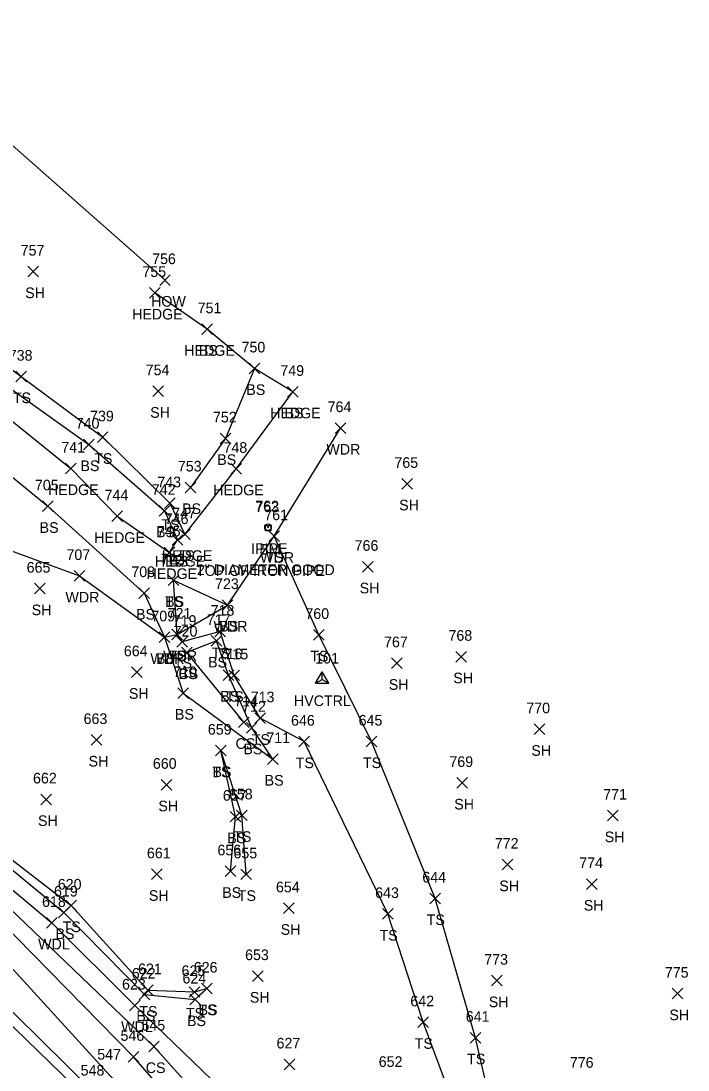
# Model space of a CAD drawing. Extents: x 1611034 to 1613847, y 761049 to 763902.
# Drawn here: x 1611914.9 to 1612040.4, y 763048.6 to 763246 of the extents above; entities that cross this region are included whole.
import ezdxf

# ---------------------------------------------------------------- set-up
doc = ezdxf.new("R2010")
doc.units = 0
for name, color, linetype in [('C_A', 7, 'Continuous'), ('C_C', 7, 'Continuous'), ('C_I', 7, 'Continuous'), ('CPBM', 7, 'Continuous'), ('CPSM', 7, 'Continuous'), ('L_A', 7, 'Continuous'), ('L_I', 7, 'Continuous'), ('L_TIC', 7, 'Continuous'), ('LAHR', 7, 'Continuous'), ('LAWA', 7, 'Continuous'), ('LBC', 7, 'Continuous'), ('LELB', 7, 'Continuous'), ('M_A', 7, 'Continuous'), ('M_C', 7, 'Continuous'), ('M_I', 7, 'Continuous'), ('MPIP', 7, 'Continuous'), ('PSP', 7, 'Continuous')]:
    doc.layers.add(name, color=color, linetype=linetype)

msp = doc.modelspace()

# ---------------------------------------------------------------- linework, layer by layer
at = {"layer": 'CPBM'}
for p, q in [((1611960.93, 763150.08), (1611960.93, 763151.08)), ((1611960.93, 763151.08), (1611961.93, 763151.08)), ((1611961.43, 763150.58), (1611961.43, 763150.58)), ((1611961.43, 763150.58), (1611961.43, 763150.58)), ((1611961.93, 763151.08), (1611961.93, 763150.08)), ((1611961.93, 763150.08), (1611960.93, 763150.08))]:
    msp.add_line(p, q, dxfattribs=at)
at = {"layer": 'CPSM'}
for p, q in [((1611970.32, 763121.37), (1611971.57, 763123.54)), ((1611972.82, 763121.37), (1611971.57, 763123.54)), ((1611971.57, 763122.09), (1611971.57, 763123.54)), ((1611970.32, 763121.37), (1611971.57, 763122.09)), ((1611970.32, 763121.37), (1611972.82, 763121.37)), ((1611971.57, 763122.09), (1611971.57, 763122.09)), ((1611971.57, 763122.09), (1611972.82, 763121.37))]:
    msp.add_line(p, q, dxfattribs=at)
at = {"layer": 'L_TIC'}
for points in [[(1611916.23, 763197.85), (1611918.23, 763199.85)], [(1611918.23, 763197.85), (1611916.23, 763199.85)], [(1611941.01, 763196.25), (1611943.01, 763198.25)], [(1611943.01, 763196.25), (1611941.01, 763198.25)], [(1611939.12, 763193.83), (1611941.12, 763195.83)], [(1611941.12, 763193.83), (1611939.12, 763195.83)], [(1611948.94, 763187), (1611950.94, 763189)], [(1611950.94, 763187), (1611948.94, 763189)], [(1611948.94, 763187), (1611950.94, 763189)], [(1611950.94, 763187), (1611948.94, 763189)], [(1611957.86, 763179.63), (1611959.86, 763181.63)], [(1611959.86, 763179.63), (1611957.86, 763181.63)], [(1611957.86, 763179.63), (1611959.86, 763181.63)], [(1611959.86, 763179.63), (1611957.86, 763181.63)], [(1611913.99, 763178.09), (1611915.99, 763180.09)], [(1611915.99, 763178.09), (1611913.99, 763180.09)], [(1611939.74, 763175.34), (1611941.74, 763177.34)], [(1611941.74, 763175.34), (1611939.74, 763177.34)], [(1611965.07, 763175.23), (1611967.07, 763177.23)], [(1611967.07, 763175.23), (1611965.07, 763177.23)], [(1611965.07, 763175.23), (1611967.07, 763177.23)], [(1611967.07, 763175.23), (1611965.07, 763177.23)], [(1611974, 763168.4), (1611976, 763170.4)], [(1611976, 763168.4), (1611974, 763170.4)], [(1611929.29, 763166.67), (1611931.29, 763168.67)], [(1611931.29, 763166.67), (1611929.29, 763168.67)], [(1611952.39, 763166.46), (1611954.39, 763168.46)], [(1611954.39, 763166.46), (1611952.39, 763168.46)], [(1611926.67, 763165.3), (1611928.67, 763167.3)], [(1611928.67, 763165.3), (1611926.67, 763167.3)], [(1611923.3, 763160.79), (1611925.3, 763162.79)], [(1611925.3, 763160.79), (1611923.3, 763162.79)], [(1611954.37, 763160.74), (1611956.37, 763162.74)], [(1611956.37, 763160.74), (1611954.37, 763162.74)], [(1611945.79, 763157.23), (1611947.79, 763159.23)], [(1611947.79, 763157.23), (1611945.79, 763159.23)], [(1611986.56, 763157.91), (1611988.56, 763159.91)], [(1611988.56, 763157.91), (1611986.56, 763159.91)], [(1611918.99, 763153.68), (1611920.99, 763155.68)], [(1611920.99, 763153.68), (1611918.99, 763155.68)], [(1611940.9, 763152.84), (1611942.9, 763154.84)], [(1611942.9, 763152.84), (1611940.9, 763154.84)], [(1611941.93, 763154.25), (1611943.93, 763156.25)], [(1611943.93, 763154.25), (1611941.93, 763156.25)], [(1611932.01, 763151.8), (1611934.01, 763153.8)], [(1611934.01, 763151.8), (1611932.01, 763153.8)], [(1611943.38, 763147.34), (1611945.38, 763149.34)], [(1611945.38, 763147.34), (1611943.38, 763149.34)], [(1611943.38, 763147.34), (1611945.38, 763149.34)], [(1611945.38, 763147.34), (1611943.38, 763149.34)], [(1611944.72, 763148.4), (1611946.72, 763150.4)], [(1611946.72, 763148.4), (1611944.72, 763150.4)], [(1611944.72, 763148.4), (1611946.72, 763150.4)], [(1611946.72, 763148.4), (1611944.72, 763150.4)], [(1611961.53, 763148.06), (1611963.53, 763150.06)], [(1611963.53, 763148.06), (1611961.53, 763150.06)], [(1611961.53, 763148.06), (1611963.53, 763150.06)], [(1611963.53, 763148.06), (1611961.53, 763150.06)], [(1611941.84, 763145), (1611943.84, 763147)], [(1611943.84, 763145), (1611941.84, 763147)], [(1611979.13, 763142.3), (1611981.13, 763144.3)], [(1611981.13, 763142.3), (1611979.13, 763144.3)], [(1611924.92, 763140.58), (1611926.92, 763142.58)], [(1611926.92, 763140.58), (1611924.92, 763142.58)], [(1611942.6, 763139.75), (1611944.6, 763141.75)], [(1611944.6, 763139.75), (1611942.6, 763141.75)], [(1611942.6, 763139.75), (1611944.6, 763141.75)], [(1611944.6, 763139.75), (1611942.6, 763141.75)], [(1611917.46, 763138.19), (1611919.46, 763140.19)], [(1611919.46, 763138.19), (1611917.46, 763140.19)], [(1611937.12, 763137.36), (1611939.12, 763139.36)], [(1611939.12, 763137.36), (1611937.12, 763139.36)], [(1611952.78, 763135.1), (1611954.78, 763137.1)], [(1611954.78, 763135.1), (1611952.78, 763137.1)], [(1611952.78, 763135.1), (1611954.78, 763137.1)], [(1611954.78, 763135.1), (1611952.78, 763137.1)], [(1611940.9, 763129.03), (1611942.9, 763131.03)], [(1611942.9, 763129.03), (1611940.9, 763131.03)], [(1611940.9, 763129.03), (1611942.9, 763131.03)], [(1611942.9, 763129.03), (1611940.9, 763131.03)], [(1611943.3, 763129.53), (1611945.3, 763131.53)], [(1611945.3, 763129.53), (1611943.3, 763131.53)], [(1611943.3, 763129.53), (1611945.3, 763131.53)], [(1611945.3, 763129.53), (1611943.3, 763131.53)], [(1611951.39, 763130.09), (1611953.39, 763132.09)], [(1611953.39, 763130.09), (1611951.39, 763132.09)], [(1611969.91, 763129.49), (1611971.91, 763131.49)], [(1611971.91, 763129.49), (1611969.91, 763131.49)], [(1611944.26, 763128.19), (1611946.26, 763130.19)], [(1611946.26, 763128.19), (1611944.26, 763130.19)], [(1611950.67, 763128.35), (1611952.67, 763130.35)], [(1611952.67, 763128.35), (1611950.67, 763130.35)], [(1611945.1, 763126.17), (1611947.1, 763128.17)], [(1611947.1, 763126.17), (1611945.1, 763128.17)], [(1611945.1, 763126.17), (1611947.1, 763128.17)], [(1611947.1, 763126.17), (1611945.1, 763128.17)], [(1611996.73, 763125.38), (1611998.73, 763127.38)], [(1611998.73, 763125.38), (1611996.73, 763127.38)], [(1611984.61, 763124.15), (1611986.61, 763126.15)], [(1611986.61, 763124.15), (1611984.61, 763126.15)], [(1611935.73, 763122.46), (1611937.73, 763124.46)], [(1611937.73, 763122.46), (1611935.73, 763124.46)], [(1611952.96, 763121.93), (1611954.96, 763123.93)], [(1611954.96, 763121.93), (1611952.96, 763123.93)], [(1611954, 763121.87), (1611956, 763123.87)], [(1611956, 763121.87), (1611954, 763123.87)], [(1611944.43, 763118.54), (1611946.43, 763120.54)], [(1611946.43, 763118.54), (1611944.43, 763120.54)], [(1611955.84, 763113.03), (1611957.84, 763115.03)], [(1611957.84, 763113.03), (1611955.84, 763115.03)], [(1611958.93, 763113.8), (1611960.93, 763115.8)], [(1611960.93, 763113.8), (1611958.93, 763115.8)], [(1611957.31, 763112.02), (1611959.31, 763114.02)], [(1611959.31, 763112.02), (1611957.31, 763114.02)], [(1612011.41, 763111.73), (1612013.41, 763113.73)], [(1612013.41, 763111.73), (1612011.41, 763113.73)], [(1611928.15, 763109.71), (1611930.15, 763111.71)], [(1611930.15, 763109.71), (1611928.15, 763111.71)], [(1611967.18, 763109.4), (1611969.18, 763111.4)], [(1611969.18, 763109.4), (1611967.18, 763111.4)], [(1611979.83, 763109.42), (1611981.83, 763111.42)], [(1611981.83, 763109.42), (1611979.83, 763111.42)], [(1611951.49, 763107.71), (1611953.49, 763109.71)], [(1611953.49, 763107.71), (1611951.49, 763109.71)], [(1611951.49, 763107.71), (1611953.49, 763109.71)], [(1611953.49, 763107.71), (1611951.49, 763109.71)], [(1611961.31, 763106.12), (1611963.31, 763108.12)], [(1611963.31, 763106.12), (1611961.31, 763108.12)], [(1611941.27, 763101.29), (1611943.27, 763103.29)], [(1611943.27, 763101.29), (1611941.27, 763103.29)], [(1611996.91, 763101.63), (1611998.91, 763103.63)], [(1611998.91, 763101.63), (1611996.91, 763103.63)], [(1611918.64, 763098.53), (1611920.64, 763100.53)], [(1611920.64, 763098.53), (1611918.64, 763100.53)], [(1611954.29, 763095.28), (1611956.29, 763097.28)], [(1611956.29, 763095.28), (1611954.29, 763097.28)], [(1611955.44, 763095.53), (1611957.44, 763097.53)], [(1611957.44, 763095.53), (1611955.44, 763097.53)], [(1612025.21, 763095.48), (1612027.21, 763097.48)], [(1612027.21, 763095.48), (1612025.21, 763097.48)], [(1612005.39, 763086.26), (1612007.39, 763088.26)], [(1612007.39, 763086.26), (1612005.39, 763088.26)], [(1611939.5, 763084.44), (1611941.5, 763086.44)], [(1611941.5, 763084.44), (1611939.5, 763086.44)], [(1611953.33, 763085), (1611955.33, 763087)], [(1611955.33, 763085), (1611953.33, 763087)], [(1611956.29, 763084.43), (1611958.29, 763086.43)], [(1611958.29, 763084.43), (1611956.29, 763086.43)], [(1612021.28, 763082.6), (1612023.28, 763084.6)], [(1612023.28, 763082.6), (1612021.28, 763084.6)], [(1611991.81, 763079.89), (1611993.81, 763081.89)], [(1611993.81, 763079.89), (1611991.81, 763081.89)], [(1611923.35, 763078.56), (1611925.35, 763080.56)], [(1611925.35, 763078.56), (1611923.35, 763080.56)], [(1611964.28, 763078.05), (1611966.28, 763080.05)], [(1611966.28, 763078.05), (1611964.28, 763080.05)], [(1611921.98, 763077.25), (1611923.98, 763079.25)], [(1611923.98, 763077.25), (1611921.98, 763079.25)], [(1611982.94, 763076.97), (1611984.94, 763078.97)], [(1611984.94, 763076.97), (1611982.94, 763078.97)], [(1611919.73, 763075.3), (1611921.73, 763077.3)], [(1611921.73, 763075.3), (1611919.73, 763077.3)], [(1611958.48, 763065.29), (1611960.48, 763067.29)], [(1611960.48, 763065.29), (1611958.48, 763067.29)], [(1612003.41, 763064.43), (1612005.41, 763066.43)], [(1612005.41, 763064.43), (1612003.41, 763066.43)], [(1611937.18, 763061.8), (1611939.18, 763063.8)], [(1611939.18, 763061.8), (1611937.18, 763063.8)], [(1611937.78, 763062.64), (1611939.78, 763064.64)], [(1611939.78, 763062.64), (1611937.78, 763064.64)], [(1611946.53, 763062.29), (1611948.53, 763064.29)], [(1611948.53, 763062.29), (1611946.53, 763064.29)], [(1611948.88, 763062.93), (1611950.88, 763064.93)], [(1611950.88, 763062.93), (1611948.88, 763064.93)], [(1611948.88, 763062.93), (1611950.88, 763064.93)], [(1611950.88, 763062.93), (1611948.88, 763064.93)], [(1612037.37, 763061.98), (1612039.37, 763063.98)], [(1612039.37, 763061.98), (1612037.37, 763063.98)], [(1611935.34, 763059.75), (1611937.34, 763061.75)], [(1611937.34, 763059.75), (1611935.34, 763061.75)], [(1611946.71, 763060.88), (1611948.71, 763062.88)], [(1611948.71, 763060.88), (1611946.71, 763062.88)], [(1611989.56, 763056.6), (1611991.56, 763058.6)], [(1611991.56, 763056.6), (1611989.56, 763058.6)], [(1611938.94, 763052.04), (1611940.94, 763054.04)], [(1611940.94, 763052.04), (1611938.94, 763054.04)], [(1611999.41, 763053.68), (1612001.41, 763055.68)], [(1612001.41, 763053.68), (1611999.41, 763055.68)], [(1611935.07, 763050.1), (1611937.07, 763052.1)], [(1611937.07, 763050.1), (1611935.07, 763052.1)], [(1611964.4, 763048.66), (1611966.4, 763050.66)], [(1611966.4, 763048.66), (1611964.4, 763050.66)]]:
    msp.add_lwpolyline(points, dxfattribs=at)
at = {"layer": 'LAHR'}
for points in [[(1611870.5, 763246), (1611861.19, 763216.3), (1611876.92, 763202.2), (1611887.58, 763190.23), (1611909.6, 763173.67), (1611924.3, 763161.79), (1611933.01, 763152.8), (1611942.84, 763146), (1611944.38, 763148.34), (1611945.72, 763149.4), (1611955.37, 763161.74), (1611966.07, 763176.23)], [(1611949.94, 763188), (1611940.12, 763194.83)]]:
    msp.add_lwpolyline(points, dxfattribs=at)
at = {"layer": 'LAWA'}
for points in [[(1611802.19, 763242.63), (1611826.4, 763223.06), (1611842.76, 763208.98), (1611848.45, 763196.15), (1611870.16, 763177.55), (1611888.93, 763166.81), (1611895.61, 763159.78), (1611907.25, 763148.44), (1611925.92, 763141.58), (1611941.9, 763130.03), (1611944.3, 763130.53), (1611953.78, 763136.1), (1611962.53, 763149.06), (1611975, 763169.4)], [(1611776.19, 763209.71), (1611798.35, 763193.21), (1611821.91, 763171.59), (1611835.23, 763154.9), (1611840.73, 763150.36), (1611854.8, 763137.66), (1611869.74, 763122.61), (1611885.36, 763108.52), (1611898.9, 763094.55), (1611920.73, 763076.3), (1611936.34, 763060.75), (1611959.95, 763037.9), (1611979.24, 763021.14), (1611992.68, 763010.08), (1612014.52, 762988.49), (1612021.56, 762990.5), (1612027.56, 763011.05)]]:
    msp.add_lwpolyline(points, dxfattribs=at)
at = {"layer": 'LBC'}
msp.add_lwpolyline([(1611905.74, 763229.24), (1611942.01, 763197.25)], dxfattribs=at)
at = {"layer": 'LELB'}
for points in [[(1611855.79, 763242.28), (1611845.15, 763223.22), (1611842.76, 763208.98), (1611861.16, 763206.26), (1611872.42, 763198.32), (1611897.21, 763173.34), (1611919.99, 763154.68), (1611938.12, 763138.36), (1611941.9, 763130.03), (1611945.43, 763119.54), (1611962.31, 763107.12), (1611958.31, 763113.02), (1611953.96, 763122.93), (1611951.67, 763129.35), (1611946.1, 763127.17)], [(1612018.61, 762964.73), (1611994.45, 762990.34), (1611965, 763017.91), (1611936.07, 763051.1), (1611910.74, 763076.87), (1611888.16, 763094.11), (1611862.22, 763121.84), (1611845.65, 763138.15), (1611819.53, 763160.99), (1611794.46, 763183.41), (1611771.91, 763204.52)], [(1611878.59, 763205.7), (1611892.17, 763196.21), (1611914.99, 763179.09), (1611930.29, 763167.67), (1611942.93, 763155.25), (1611945.72, 763149.4)], [(1611878.59, 763205.7), (1611890.96, 763193.26), (1611912.74, 763176.97), (1611927.67, 763166.3), (1611941.9, 763153.84), (1611944.38, 763148.34)], [(1612017.14, 762963.27), (1611992.31, 762988.18), (1611962.87, 763016.31), (1611931.63, 763047.56), (1611908.18, 763073.24), (1611886.96, 763093.2), (1611860.29, 763119.05), (1611842.79, 763135.64), (1611817.54, 763159.12), (1611792.58, 763181.1), (1611769.85, 763202.31)], [(1612014.39, 762960.1), (1611988.81, 762984.91), (1611960.67, 763014.03), (1611928.51, 763044.56), (1611903.94, 763068.78), (1611882.15, 763089), (1611856.04, 763113.65), (1611837.67, 763131.07), (1611812.66, 763153.54), (1611788.39, 763176.44), (1611765.16, 763197.77)], [(1611966.07, 763176.23), (1611958.86, 763180.63), (1611949.94, 763188)], [(1611827.47, 763182.21), (1611834.78, 763166.48), (1611843.63, 763154.27), (1611859.28, 763139.94), (1611873.14, 763124.64), (1611887.96, 763110.58), (1611901.84, 763096.95), (1611924.35, 763079.56), (1611938.78, 763063.64), (1611947.53, 763063.29), (1611949.88, 763063.93)], [(1611826.18, 763181.01), (1611833.29, 763165.33), (1611843.02, 763153.57), (1611858.69, 763138.62), (1611871.83, 763124.3), (1611887.15, 763109.94), (1611901.05, 763096.37), (1611922.98, 763078.25), (1611938.18, 763062.8), (1611947.71, 763061.88), (1611949.88, 763063.93)], [(1611958.86, 763180.63), (1611953.39, 763167.46), (1611946.79, 763158.23)], [(1612027.83, 762976.33), (1612021.56, 762990.5), (1612007.15, 763025.37), (1612000.41, 763054.68), (1611992.81, 763080.89), (1611980.83, 763110.42), (1611970.91, 763130.49), (1611962.53, 763149.06)], [(1612025.16, 762973.81), (1612014.52, 762988.49), (1612002.76, 763024.77), (1611990.56, 763057.6), (1611983.94, 763077.97), (1611968.18, 763110.4), (1611959.93, 763114.8), (1611955, 763122.87), (1611952.39, 763131.09), (1611945.26, 763129.19), (1611944.3, 763130.53), (1611943.6, 763140.75)], [(1611943.6, 763140.75), (1611953.78, 763136.1)], [(1611956.84, 763114.03), (1611946.1, 763127.17)], [(1611994.45, 762990.34), (1611968.15, 763021.56), (1611939.94, 763053.04), (1611912.82, 763078.99), (1611895.55, 763090.9), (1611891.53, 763096.94), (1611862.22, 763121.84)], [(1611957.29, 763085.43), (1611956.44, 763096.53), (1611952.49, 763108.71)], [(1611954.33, 763086), (1611955.29, 763096.28), (1611952.49, 763108.71)]]:
    msp.add_lwpolyline(points, dxfattribs=at)
at = {"layer": 'MPIP'}
for radius in [0.625, 0.0833]:
    msp.add_circle((1611961.38, 763150.73), radius, dxfattribs=at)
at = {"layer": 'PSP'}
msp.add_lwpolyline([(1612013.06, 762958.69), (1611987.98, 762983.85), (1611959.05, 763012.61), (1611927.06, 763043.5), (1611902.53, 763067.25), (1611880.81, 763087.35), (1611854.34, 763111.86), (1611835.7, 763129.09), (1611811.01, 763152.07), (1611786.17, 763174.66), (1611763.42, 763195.74)], dxfattribs=at)

# ---------------------------------------------------------------- texts
at = {"layer": 'C_A'}
for s, p in [('BM', (1611959.75, 763145.58)), ('HVCTRL', (1611966.26, 763117.09))]:
    msp.add_text(s, height=2, dxfattribs=at).set_placement(p)
at = {"layer": 'C_C'}
msp.add_text('TOP OF IRON PIPE', height=2, dxfattribs=at).set_placement((1611947.84, 763141.58))
at = {"layer": 'C_I'}
for s, p in [('763', (1611959.02, 763153.58)), ('101', (1611970.26, 763125.09))]:
    msp.add_text(s, height=2, dxfattribs=at).set_placement(p)
at = {"layer": 'L_A'}
for s, p in [('SH', (1611915.72, 763193.85)), ('HOW', (1611939.39, 763192.25)), ('HEDGE', (1611935.82, 763189.83)), ('HEDGE', (1611945.64, 763183)), ('BS', (1611948.38, 763183)), ('BS', (1611957.3, 763175.63)), ('BS', (1611957.3, 763175.63)), ('TS', (1611913.4, 763174.09)), ('SH', (1611939.23, 763171.34)), ('HEDGE', (1611961.77, 763171.23)), ('BS', (1611964.51, 763171.23)), ('WDR', (1611972.36, 763164.4)), ('TS', (1611928.7, 763162.67)), ('BS', (1611951.83, 763162.46)), ('BS', (1611926.11, 763161.3)), ('HEDGE', (1611920.01, 763156.79)), ('HEDGE', (1611951.07, 763156.74)), ('BS', (1611945.23, 763153.23)), ('SH', (1611986.05, 763153.91)), ('BS', (1611918.43, 763149.68)), ('BS', (1611940.34, 763148.84)), ('TS', (1611941.34, 763150.25)), ('HEDGE', (1611928.71, 763147.8)), ('HEDGE', (1611940.09, 763143.34)), ('HEDGE', (1611941.42, 763144.4)), ('BS', (1611942.83, 763143.34)), ('TS', (1611944.13, 763144.4)), ('WDR', (1611959.89, 763144.06)), ('TS', (1611960.94, 763144.06)), ('HEDGE', (1611938.54, 763141)), ('SH', (1611978.62, 763138.3)), ('WDR', (1611923.29, 763136.58)), ('TS', (1611942.01, 763135.75)), ('BS', (1611942.04, 763135.75)), ('SH', (1611916.94, 763134.19)), ('BS', (1611936.56, 763133.36)), ('WDR', (1611951.14, 763131.1)), ('BS', (1611952.22, 763131.1)), ('WDR', (1611939.26, 763125.03)), ('BS', (1611940.34, 763125.03)), ('WDR', (1611941.66, 763125.53)), ('TS', (1611942.71, 763125.53)), ('TS', (1611950.8, 763126.09)), ('TS', (1611969.32, 763125.49)), ('TS', (1611943.67, 763124.19)), ('BS', (1611950.11, 763124.35)), ('CS', (1611944.54, 763122.17)), ('BS', (1611944.54, 763122.17)), ('SH', (1611996.22, 763121.38)), ('SH', (1611984.1, 763120.15)), ('SH', (1611935.22, 763118.46)), ('BS', (1611952.4, 763117.93)), ('TS', (1611953.41, 763117.87)), ('BS', (1611943.87, 763114.54)), ('CS', (1611955.28, 763109.03)), ('TS', (1611958.34, 763109.8)), ('BS', (1611956.75, 763108.02)), ('SH', (1612010.9, 763107.73)), ('SH', (1611927.64, 763105.71)), ('TS', (1611966.59, 763105.4)), ('TS', (1611979.24, 763105.42)), ('TS', (1611950.9, 763103.71)), ('BS', (1611950.93, 763103.71)), ('BS', (1611960.75, 763102.12)), ('SH', (1611940.76, 763097.29)), ('SH', (1611996.4, 763097.63)), ('SH', (1611918.13, 763094.53)), ('BS', (1611953.73, 763091.28)), ('TS', (1611954.84, 763091.53)), ('SH', (1612024.7, 763091.48)), ('SH', (1612004.88, 763082.26)), ('SH', (1611938.98, 763080.44)), ('BS', (1611952.77, 763081)), ('TS', (1611955.7, 763080.43)), ('SH', (1612020.76, 763078.6)), ('TS', (1611991.22, 763075.89)), ('TS', (1611922.76, 763074.56)), ('SH', (1611963.76, 763074.05)), ('BS', (1611921.42, 763073.25)), ('TS', (1611982.35, 763072.97)), ('WDL', (1611918.15, 763071.3)), ('SH', (1611957.97, 763061.29)), ('SH', (1612002.9, 763060.43)), ('BS', (1611936.62, 763057.8)), ('TS', (1611937.19, 763058.64)), ('TS', (1611945.94, 763058.29)), ('TS', (1611948.29, 763058.93)), ('BS', (1611948.32, 763058.93)), ('SH', (1612036.86, 763057.98)), ('WDL', (1611933.76, 763055.75)), ('BS', (1611946.15, 763056.88)), ('TS', (1611988.97, 763052.6)), ('CS', (1611938.39, 763048.04)), ('TS', (1611998.82, 763049.68))]:
    msp.add_text(s, height=2, dxfattribs=at).set_placement(p)
at = {"layer": 'L_I'}
for s, p in [('757', (1611914.87, 763201.85)), ('756', (1611939.59, 763200.25)), ('755', (1611937.76, 763197.83)), ('751', (1611948.15, 763191)), ('751', (1611948.15, 763191)), ('738', (1611912.63, 763182.09)), ('750', (1611956.41, 763183.63)), ('750', (1611956.41, 763183.63)), ('754', (1611938.38, 763179.34)), ('749', (1611963.7, 763179.23)), ('749', (1611963.7, 763179.23)), ('764', (1611972.59, 763172.4)), ('739', (1611927.92, 763170.67)), ('752', (1611951.03, 763170.46)), ('740', (1611925.22, 763169.3)), ('741', (1611922.51, 763164.79)), ('748', (1611953.01, 763164.74)), ('753', (1611944.43, 763161.23)), ('765', (1611985.15, 763161.91)), ('705', (1611917.55, 763157.68)), ('742', (1611939.53, 763156.84)), ('743', (1611940.57, 763158.25)), ('744', (1611930.65, 763155.8)), ('746', (1611941.97, 763151.34)), ('746', (1611941.97, 763151.34)), ('747', (1611943.36, 763152.4)), ('747', (1611943.36, 763152.4)), ('761', (1611960.68, 763152.06)), ('761', (1611960.68, 763152.06)), ('745', (1611940.48, 763149)), ('707', (1611923.48, 763144.58)), ('766', (1611977.67, 763146.3)), ('722', (1611941.24, 763143.75)), ('722', (1611941.24, 763143.75)), ('665', (1611916, 763142.19)), ('708', (1611935.68, 763141.36)), ('723', (1611951.42, 763139.1)), ('723', (1611951.42, 763139.1)), ('709', (1611939.45, 763133.03)), ('709', (1611939.45, 763133.03)), ('721', (1611942.5, 763133.53)), ('721', (1611942.5, 763133.53)), ('718', (1611950.6, 763134.09)), ('760', (1611968.41, 763133.49)), ('719', (1611943.46, 763132.19)), ('717', (1611949.87, 763132.35)), ('720', (1611943.65, 763130.17)), ('720', (1611943.65, 763130.17)), ('768', (1611995.32, 763129.38)), ('767', (1611983.2, 763128.15)), ('664', (1611934.27, 763126.46)), ('716', (1611952.11, 763125.93)), ('715', (1611953.2, 763125.87)), ('710', (1611943.55, 763122.54)), ('714', (1611955.04, 763117.03)), ('713', (1611958.13, 763117.8)), ('712', (1611956.51, 763116.02)), ('770', (1612009.96, 763115.73)), ('663', (1611926.7, 763113.71)), ('646', (1611965.71, 763113.4)), ('645', (1611978.42, 763113.42)), ('659', (1611950.07, 763111.71)), ('659', (1611950.07, 763111.71)), ('711', (1611961.08, 763110.12)), ('660', (1611939.73, 763105.29)), ('769', (1611995.49, 763105.63)), ('662', (1611917.19, 763102.53)), ('657', (1611952.88, 763099.28)), ('658', (1611954.03, 763099.53)), ('771', (1612024.42, 763099.48)), ('772', (1612004.03, 763090.26)), ('661', (1611938.61, 763088.44)), ('656', (1611951.87, 763089)), ('655', (1611954.88, 763088.43)), ('774', (1612019.91, 763086.6)), ('644', (1611990.4, 763083.89)), ('620', (1611921.85, 763082.56)), ('654', (1611962.87, 763082.05)), ('619', (1611921.13, 763081.25)), ('643', (1611981.53, 763080.97)), ('618', (1611918.89, 763079.3)), ('653', (1611957.07, 763069.29)), ('773', (1612002.05, 763068.43)), ('622', (1611935.77, 763065.8)), ('621', (1611936.94, 763066.64)), ('625', (1611945.12, 763066.29)), ('626', (1611947.42, 763066.93)), ('626', (1611947.42, 763066.93)), ('775', (1612036.01, 763065.98)), ('623', (1611933.93, 763063.75)), ('624', (1611945.3, 763064.88)), ('642', (1611988.15, 763060.6)), ('641', (1611998.57, 763057.68)), ('545', (1611937.58, 763056.04)), ('546', (1611933.65, 763054.1)), ('627', (1611962.99, 763052.66)), ('547', (1611929.27, 763050.56)), ('652', (1611982.2, 763049.19)), ('776', (1612018.14, 763049.03)), ('548', (1611926.15, 763047.56))]:
    msp.add_text(s, height=2, dxfattribs=at).set_placement(p)
at = {"layer": 'M_A'}
msp.add_text('IPIPE', height=2, dxfattribs=at).set_placement((1611958.21, 763145.73))
at = {"layer": 'M_C'}
msp.add_text('2" DIAMETER GOOD', height=2, dxfattribs=at).set_placement((1611948, 763141.73))
at = {"layer": 'M_I'}
msp.add_text('762', height=2, dxfattribs=at).set_placement((1611958.97, 763153.73))

doc.saveas('drawing.dxf')
